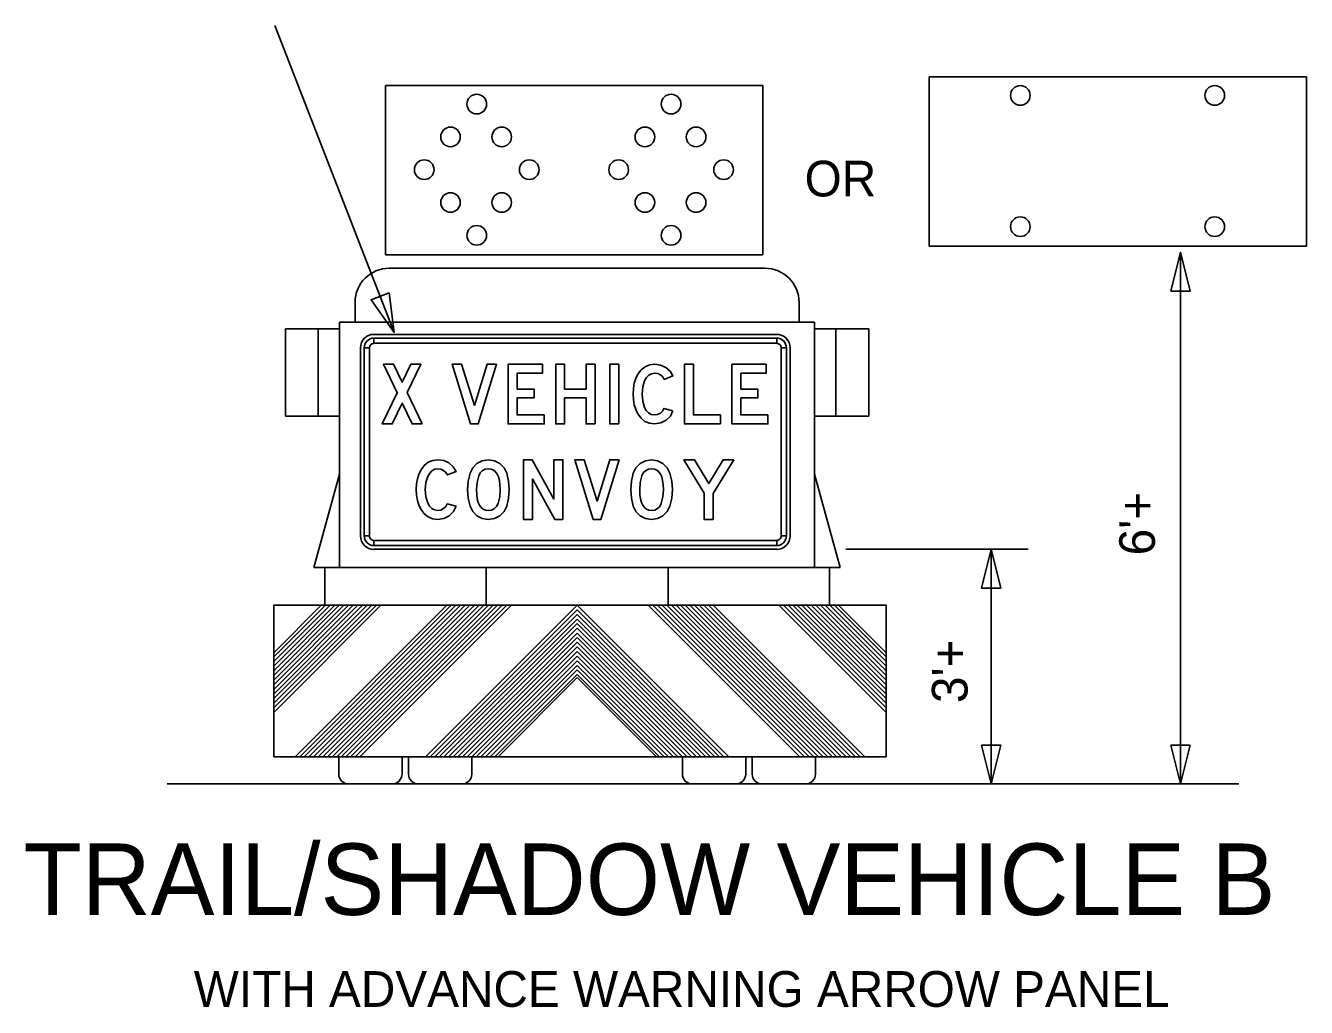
# Model space of a CAD drawing. Extents: x 1806907 to 1812607, y 675071 to 676228.
# Drawn here: x 1811772.8 to 1811988.1, y 675569.5 to 675734.4 of the extents above; entities that cross this region are included whole.
import ezdxf

# ---------------------------------------------------------------- set-up
doc = ezdxf.new("R2010")
doc.units = 0
doc.layers.add('Working Level 1', color=7, linetype='Continuous')

msp = doc.modelspace()

# ---------------------------------------------------------------- linework, layer by layer
at = {"layer": 'Working Level 1'}
for p, q in [((1811834.74, 675682.89), (1811814.73, 675734.43)), ((1811924.67, 675697.37), (1811924.67, 675725.81)), ((1811924.67, 675725.81), (1811988.1, 675725.81)), ((1811988.1, 675697.37), (1811988.1, 675725.81)), ((1811833.29, 675724.36), (1811896.72, 675724.36)), ((1811833.29, 675695.92), (1811833.29, 675724.36)), ((1811896.72, 675695.92), (1811896.72, 675724.36)), ((1811924.67, 675697.37), (1811988.1, 675697.37)), ((1811833.29, 675695.92), (1811896.72, 675695.92)), ((1811966.95, 675607.04), (1811966.95, 675696.35)), ((1811966.95, 675696.35), (1811966.95, 675691.11)), ((1811833.95, 675693.67), (1811897.09, 675693.67)), ((1811828.2, 675684.64), (1811828.2, 675687.94)), ((1811902.83, 675684.64), (1811902.83, 675687.94)), ((1811825.6, 675643.38), (1811825.6, 675684.64)), ((1811825.6, 675684.64), (1811905.43, 675684.64)), ((1811905.43, 675643.38), (1811905.43, 675684.64)), ((1811816.49, 675668.81), (1811816.49, 675683.48)), ((1811816.49, 675683.48), (1811825.6, 675683.48)), ((1811822.01, 675668.81), (1811822.01, 675683.48)), ((1811899.06, 675682.57), (1811831.35, 675682.57)), ((1811831.35, 675681.07), (1811831.35, 675681.94)), ((1811899.06, 675681.94), (1811899.06, 675681.07)), ((1811914.54, 675683.48), (1811905.43, 675683.48)), ((1811909.02, 675668.81), (1811909.02, 675683.48)), ((1811914.54, 675668.81), (1811914.54, 675683.48)), ((1811829.09, 675680.31), (1811829.09, 675648.71)), ((1811829.72, 675680.31), (1811830.59, 675680.31)), ((1811899.81, 675680.31), (1811900.69, 675680.31)), ((1811901.32, 675648.71), (1811901.32, 675680.31)), ((1811816.49, 675668.81), (1811825.6, 675668.81)), ((1811914.54, 675668.81), (1811905.43, 675668.81)), ((1811825.6, 675659.1), (1811821.28, 675643.38)), ((1811905.43, 675659.1), (1811909.75, 675643.38)), ((1811830.59, 675648.71), (1811829.72, 675648.71)), ((1811831.35, 675647.08), (1811831.35, 675647.96)), ((1811899.06, 675647.96), (1811899.06, 675647.08)), ((1811900.69, 675648.71), (1811899.81, 675648.71)), ((1811831.35, 675646.46), (1811899.06, 675646.46)), ((1811910.69, 675646.46), (1811941.31, 675646.46)), ((1811935.14, 675607.04), (1811935.14, 675646.46)), ((1811935.14, 675646.46), (1811935.14, 675641.13)), ((1811821.28, 675643.38), (1811909.75, 675643.38)), ((1811823.08, 675637.07), (1811823.08, 675643.38)), ((1811850.2, 675637.07), (1811850.2, 675643.26)), ((1811880.83, 675637.07), (1811880.83, 675643.26)), ((1811907.95, 675637.07), (1811907.95, 675643.38)), ((1811814.51, 675637.07), (1811917.46, 675637.07)), ((1811814.51, 675637.07), (1811917.46, 675637.07)), ((1811814.51, 675637.07), (1811917.46, 675637.07)), ((1811814.51, 675637.07), (1811917.46, 675637.07)), ((1811814.51, 675611.58), (1811814.51, 675637.07)), ((1811814.51, 675629.09), (1811822.49, 675637.07)), ((1811814.51, 675619.81), (1811831.77, 675637.07)), ((1811814.51, 675620.6), (1811830.99, 675637.07)), ((1811814.51, 675621.38), (1811830.21, 675637.07)), ((1811814.51, 675622.15), (1811829.44, 675637.07)), ((1811814.51, 675622.93), (1811828.65, 675637.07)), ((1811814.51, 675623.71), (1811827.87, 675637.07)), ((1811814.51, 675624.48), (1811827.1, 675637.07)), ((1811814.51, 675625.26), (1811826.32, 675637.07)), ((1811814.51, 675626.04), (1811825.54, 675637.07)), ((1811814.51, 675626.82), (1811824.76, 675637.07)), ((1811814.51, 675627.59), (1811823.99, 675637.07)), ((1811814.51, 675628.37), (1811823.21, 675637.07)), ((1811814.51, 675619.04), (1811832.52, 675637.05)), ((1811818.1, 675611.58), (1811843.6, 675637.07)), ((1811818.88, 675611.58), (1811844.37, 675637.07)), ((1811819.66, 675611.58), (1811845.15, 675637.07)), ((1811820.44, 675611.58), (1811845.94, 675637.07)), ((1811821.21, 675611.58), (1811846.71, 675637.07)), ((1811821.99, 675611.58), (1811847.49, 675637.07)), ((1811822.77, 675611.58), (1811848.27, 675637.07)), ((1811823.55, 675611.58), (1811849.05, 675637.07)), ((1811824.32, 675611.58), (1811849.82, 675637.07)), ((1811825.1, 675611.58), (1811850.6, 675637.07)), ((1811825.88, 675611.58), (1811851.38, 675637.07)), ((1811826.65, 675611.58), (1811852.15, 675637.07)), ((1811827.43, 675611.58), (1811852.93, 675637.07)), ((1811828.21, 675611.58), (1811853.7, 675637.06)), ((1811828.99, 675611.58), (1811854.49, 675637.07)), ((1811840.02, 675611.58), (1811865.52, 675637.07)), ((1811891.01, 675611.58), (1811865.52, 675637.07)), ((1811902.98, 675611.58), (1811877.48, 675637.07)), ((1811903.75, 675611.58), (1811878.26, 675637.06)), ((1811904.53, 675611.58), (1811879.03, 675637.07)), ((1811905.31, 675611.58), (1811879.82, 675637.07)), ((1811906.08, 675611.58), (1811880.59, 675637.07)), ((1811906.86, 675611.58), (1811881.37, 675637.07)), ((1811907.65, 675611.58), (1811882.15, 675637.07)), ((1811908.42, 675611.58), (1811882.92, 675637.07)), ((1811909.2, 675611.58), (1811883.7, 675637.07)), ((1811909.98, 675611.58), (1811884.48, 675637.07)), ((1811910.76, 675611.58), (1811885.26, 675637.07)), ((1811911.53, 675611.58), (1811886.03, 675637.07)), ((1811912.31, 675611.58), (1811886.81, 675637.07)), ((1811913.09, 675611.58), (1811887.59, 675637.07)), ((1811913.87, 675611.58), (1811888.37, 675637.07)), ((1811917.46, 675619.04), (1811899.44, 675637.05)), ((1811917.46, 675619.81), (1811900.2, 675637.07)), ((1811917.46, 675620.6), (1811900.98, 675637.07)), ((1811917.46, 675621.38), (1811901.76, 675637.07)), ((1811917.46, 675622.15), (1811902.53, 675637.07)), ((1811917.46, 675622.93), (1811903.31, 675637.07)), ((1811917.46, 675623.71), (1811904.09, 675637.07)), ((1811917.46, 675624.48), (1811904.86, 675637.07)), ((1811917.46, 675625.26), (1811905.64, 675637.07)), ((1811917.46, 675626.04), (1811906.42, 675637.07)), ((1811917.46, 675626.82), (1811907.21, 675637.07)), ((1811917.46, 675627.59), (1811907.98, 675637.07)), ((1811917.46, 675628.37), (1811908.76, 675637.07)), ((1811917.46, 675629.09), (1811909.48, 675637.07)), ((1811917.46, 675611.58), (1811917.46, 675637.07)), ((1811840.79, 675611.58), (1811865.52, 675636.3)), ((1811841.57, 675611.58), (1811865.52, 675635.52)), ((1811842.35, 675611.58), (1811865.52, 675634.74)), ((1811890.2, 675611.62), (1811865.52, 675636.3)), ((1811889.46, 675611.58), (1811865.52, 675635.52)), ((1811888.68, 675611.58), (1811865.52, 675634.74)), ((1811843.12, 675611.58), (1811865.52, 675633.97)), ((1811843.91, 675611.58), (1811865.52, 675633.19)), ((1811844.69, 675611.58), (1811865.52, 675632.4)), ((1811887.91, 675611.58), (1811865.52, 675633.97)), ((1811887.13, 675611.58), (1811865.52, 675633.19)), ((1811886.35, 675611.58), (1811865.52, 675632.4)), ((1811845.46, 675611.58), (1811865.52, 675631.63)), ((1811846.24, 675611.58), (1811865.52, 675630.85)), ((1811847.02, 675611.58), (1811865.52, 675630.07)), ((1811885.58, 675611.58), (1811865.52, 675631.63)), ((1811884.8, 675611.58), (1811865.52, 675630.85)), ((1811884.02, 675611.58), (1811865.52, 675630.07)), ((1811847.8, 675611.58), (1811865.52, 675629.29)), ((1811848.57, 675611.58), (1811865.52, 675628.52)), ((1811883.24, 675611.58), (1811865.52, 675629.29)), ((1811882.47, 675611.58), (1811865.52, 675628.52)), ((1811849.35, 675611.58), (1811865.52, 675627.74)), ((1811850.13, 675611.58), (1811865.52, 675626.96)), ((1811850.9, 675611.58), (1811865.52, 675626.19)), ((1811881.69, 675611.58), (1811865.52, 675627.74)), ((1811880.9, 675611.58), (1811865.52, 675626.96)), ((1811880.13, 675611.58), (1811865.52, 675626.19)), ((1811851.68, 675611.58), (1811865.52, 675625.41)), ((1811852.33, 675611.72), (1811865.52, 675624.91)), ((1811879.35, 675611.58), (1811865.52, 675625.41)), ((1811878.85, 675611.58), (1811865.52, 675624.91)), ((1811814.51, 675611.58), (1811917.46, 675611.58)), ((1811814.51, 675611.58), (1811917.46, 675611.58)), ((1811814.51, 675611.58), (1811917.46, 675611.58)), ((1811814.51, 675611.58), (1811917.46, 675611.58)), ((1811825.45, 675608.69), (1811825.45, 675611.58)), ((1811836.08, 675608.69), (1811836.08, 675611.58)), ((1811837.18, 675608.69), (1811837.18, 675611.58)), ((1811847.82, 675608.69), (1811847.82, 675611.58)), ((1811883.21, 675608.69), (1811883.21, 675611.58)), ((1811893.85, 675608.69), (1811893.85, 675611.58)), ((1811894.95, 675608.69), (1811894.95, 675611.58)), ((1811905.58, 675608.69), (1811905.58, 675611.58)), ((1811796.63, 675607.04), (1811976.74, 675607.04)), ((1811825.45, 675607.04), (1811836.08, 675607.04)), ((1811825.45, 675607.04), (1811836.08, 675607.04)), ((1811825.45, 675607.04), (1811836.08, 675607.04)), ((1811825.45, 675607.04), (1811836.08, 675607.04)), ((1811837.18, 675607.04), (1811847.82, 675607.04)), ((1811837.18, 675607.04), (1811847.82, 675607.04)), ((1811837.18, 675607.04), (1811847.82, 675607.04)), ((1811837.18, 675607.04), (1811847.82, 675607.04)), ((1811893.85, 675607.04), (1811883.21, 675607.04)), ((1811893.85, 675607.04), (1811883.21, 675607.04)), ((1811893.85, 675607.04), (1811883.21, 675607.04)), ((1811893.85, 675607.04), (1811883.21, 675607.04)), ((1811905.58, 675607.04), (1811894.95, 675607.04)), ((1811905.58, 675607.04), (1811894.95, 675607.04)), ((1811905.58, 675607.04), (1811894.95, 675607.04)), ((1811905.58, 675607.04), (1811894.95, 675607.04))]:
    msp.add_line(p, q, dxfattribs=at)
for points in [[(1811965.32, 675689.85), (1811966.95, 675696.35), (1811968.57, 675689.85)], [(1811833.91, 675689.53), (1811834.74, 675682.89), (1811830.88, 675688.36)], [(1811899.06, 675681.94), (1811831.35, 675681.94), (1811831.35, 675681.07), (1811899.06, 675681.07), (1811899.06, 675681.94)], [(1811829.72, 675680.31), (1811829.72, 675648.71), (1811830.59, 675648.71), (1811830.59, 675680.31), (1811829.72, 675680.31)], [(1811900.69, 675648.71), (1811900.69, 675680.31), (1811899.81, 675680.31), (1811899.81, 675648.71), (1811900.69, 675648.71)], [(1811839.45, 675667.52), (1811836.95, 675672.78), (1811839.24, 675677.55), (1811837.57, 675677.55), (1811836.11, 675674.53), (1811834.67, 675677.55), (1811832.99, 675677.55), (1811835.27, 675672.77), (1811832.76, 675667.52), (1811834.43, 675667.52), (1811836.11, 675671.01), (1811837.77, 675667.52)], [(1811851.98, 675677.55), (1811850.4, 675677.55), (1811848.24, 675670.62), (1811846.09, 675677.55), (1811844.51, 675677.55), (1811847.62, 675667.52), (1811848.86, 675667.52)], [(1811859.98, 675669.04), (1811855.43, 675669.04), (1811855.43, 675671.88), (1811858.27, 675671.88), (1811858.27, 675673.39), (1811855.43, 675673.39), (1811855.43, 675676.04), (1811859.67, 675676.04), (1811859.67, 675677.55), (1811853.92, 675677.55), (1811853.92, 675667.52), (1811859.98, 675667.52)], [(1811868.53, 675667.52), (1811868.53, 675677.55), (1811867.02, 675677.55), (1811867.02, 675673.39), (1811863.42, 675673.39), (1811863.42, 675677.55), (1811861.91, 675677.55), (1811861.91, 675667.52), (1811863.42, 675667.52), (1811863.42, 675671.88), (1811867.02, 675671.88), (1811867.02, 675667.52)], [(1811872.52, 675667.52), (1811872.52, 675677.55), (1811871, 675677.55), (1811871, 675667.52)], [(1811881.62, 675669.75), (1811880.1, 675670.13), (1811879.87, 675669.69), (1811879.51, 675669.34), (1811879.04, 675669.11), (1811878.51, 675669.04), (1811877.99, 675669.12), (1811877.53, 675669.36), (1811877.15, 675669.76), (1811876.85, 675670.31), (1811876.54, 675671.34), (1811876.44, 675672.54), (1811876.54, 675673.74), (1811876.86, 675674.77), (1811877.17, 675675.33), (1811877.57, 675675.72), (1811878.03, 675675.96), (1811878.56, 675676.04), (1811879.06, 675675.97), (1811879.52, 675675.76), (1811879.9, 675675.43), (1811880.16, 675675.01), (1811881.62, 675675.59), (1811881.13, 675676.39), (1811880.41, 675677.02), (1811879.54, 675677.42), (1811878.59, 675677.55), (1811877.7, 675677.45), (1811876.93, 675677.14), (1811876.28, 675676.61), (1811875.73, 675675.88), (1811875.37, 675675.16), (1811875.12, 675674.36), (1811874.97, 675673.49), (1811874.92, 675672.54), (1811874.97, 675671.6), (1811875.12, 675670.73), (1811875.37, 675669.94), (1811875.72, 675669.22), (1811876.26, 675668.47), (1811876.91, 675667.95), (1811877.67, 675667.63), (1811878.54, 675667.52), (1811879.56, 675667.68), (1811880.47, 675668.14), (1811881.19, 675668.85)], [(1811889.61, 675667.52), (1811889.61, 675669.04), (1811885.06, 675669.04), (1811885.06, 675677.55), (1811883.54, 675677.55), (1811883.54, 675667.52)], [(1811897.6, 675669.04), (1811893.05, 675669.04), (1811893.05, 675671.88), (1811895.89, 675671.88), (1811895.89, 675673.39), (1811893.05, 675673.39), (1811893.05, 675676.04), (1811897.29, 675676.04), (1811897.29, 675677.55), (1811891.54, 675677.55), (1811891.54, 675667.52), (1811897.6, 675667.52)], [(1811845.17, 675653.7), (1811843.65, 675654.08), (1811843.43, 675653.64), (1811843.06, 675653.29), (1811842.59, 675653.06), (1811842.07, 675652.99), (1811841.54, 675653.07), (1811841.09, 675653.31), (1811840.71, 675653.71), (1811840.4, 675654.26), (1811840.09, 675655.29), (1811839.99, 675656.49), (1811840.09, 675657.69), (1811840.41, 675658.72), (1811840.73, 675659.28), (1811841.12, 675659.67), (1811841.58, 675659.91), (1811842.12, 675659.99), (1811842.62, 675659.92), (1811843.08, 675659.71), (1811843.46, 675659.38), (1811843.72, 675658.96), (1811845.17, 675659.53), (1811844.68, 675660.34), (1811843.97, 675660.97), (1811843.1, 675661.37), (1811842.14, 675661.5), (1811841.26, 675661.4), (1811840.49, 675661.08), (1811839.83, 675660.56), (1811839.28, 675659.83), (1811838.93, 675659.11), (1811838.68, 675658.31), (1811838.53, 675657.44), (1811838.48, 675656.49), (1811838.52, 675655.55), (1811838.67, 675654.68), (1811838.92, 675653.89), (1811839.28, 675653.16), (1811839.81, 675652.42), (1811840.46, 675651.9), (1811841.22, 675651.58), (1811842.09, 675651.47), (1811843.11, 675651.63), (1811844.03, 675652.09), (1811844.75, 675652.8)], [(1811854.1, 675656.49), (1811854, 675657.93), (1811853.69, 675659.27), (1811853.24, 675660.17), (1811852.52, 675660.89), (1811851.61, 675661.35), (1811850.59, 675661.5), (1811849.57, 675661.35), (1811848.67, 675660.89), (1811847.96, 675660.17), (1811847.51, 675659.26), (1811847.2, 675657.92), (1811847.1, 675656.49), (1811847.2, 675655.07), (1811847.51, 675653.73), (1811847.96, 675652.82), (1811848.67, 675652.1), (1811849.57, 675651.63), (1811850.59, 675651.47), (1811851.61, 675651.63), (1811852.52, 675652.09), (1811853.23, 675652.8), (1811853.68, 675653.71), (1811853.99, 675655.06)], [(1811863.13, 675651.47), (1811863.13, 675661.5), (1811861.61, 675661.5), (1811861.61, 675654.91), (1811857.96, 675661.5), (1811856.5, 675661.5), (1811856.5, 675651.47), (1811858.02, 675651.47), (1811858.02, 675658.28), (1811861.79, 675651.47)], [(1811872.59, 675661.5), (1811871.01, 675661.5), (1811868.86, 675654.57), (1811866.71, 675661.5), (1811865.12, 675661.5), (1811868.23, 675651.47), (1811869.48, 675651.47)], [(1811881.53, 675656.49), (1811881.43, 675657.93), (1811881.12, 675659.27), (1811880.67, 675660.17), (1811879.95, 675660.89), (1811879.04, 675661.35), (1811878.02, 675661.5), (1811877, 675661.35), (1811876.1, 675660.89), (1811875.39, 675660.17), (1811874.94, 675659.26), (1811874.63, 675657.92), (1811874.53, 675656.49), (1811874.63, 675655.07), (1811874.94, 675653.73), (1811875.39, 675652.82), (1811876.1, 675652.1), (1811877, 675651.63), (1811878.02, 675651.47), (1811879.04, 675651.63), (1811879.95, 675652.09), (1811880.66, 675652.8), (1811881.12, 675653.71), (1811881.42, 675655.06)], [(1811891.87, 675661.5), (1811890.09, 675661.5), (1811887.63, 675657.5), (1811885.23, 675661.5), (1811883.46, 675661.5), (1811886.87, 675655.87), (1811886.87, 675651.47), (1811888.38, 675651.47), (1811888.38, 675655.83)], [(1811852.59, 675656.49), (1811852.5, 675655.27), (1811852.23, 675654.14), (1811851.99, 675653.66), (1811851.61, 675653.3), (1811851.14, 675653.06), (1811850.61, 675652.99), (1811850.14, 675653.04), (1811849.73, 675653.21), (1811849.39, 675653.48), (1811849.11, 675653.86), (1811848.89, 675654.35), (1811848.74, 675654.96), (1811848.64, 675655.67), (1811848.61, 675656.49), (1811848.7, 675657.7), (1811848.97, 675658.83), (1811849.21, 675659.3), (1811849.58, 675659.67), (1811850.06, 675659.91), (1811850.61, 675659.99), (1811851.07, 675659.93), (1811851.47, 675659.77), (1811851.81, 675659.5), (1811852.09, 675659.11), (1811852.31, 675658.62), (1811852.46, 675658.02), (1811852.55, 675657.31)], [(1811880.02, 675656.49), (1811879.93, 675655.27), (1811879.66, 675654.14), (1811879.42, 675653.66), (1811879.04, 675653.3), (1811878.57, 675653.06), (1811878.04, 675652.99), (1811877.57, 675653.04), (1811877.16, 675653.21), (1811876.82, 675653.48), (1811876.54, 675653.86), (1811876.32, 675654.35), (1811876.17, 675654.96), (1811876.07, 675655.67), (1811876.04, 675656.49), (1811876.13, 675657.7), (1811876.4, 675658.83), (1811876.64, 675659.3), (1811877.01, 675659.67), (1811877.49, 675659.91), (1811878.04, 675659.99), (1811878.5, 675659.93), (1811878.9, 675659.77), (1811879.24, 675659.5), (1811879.52, 675659.11), (1811879.74, 675658.62), (1811879.89, 675658.02), (1811879.98, 675657.31)], [(1811831.35, 675647.08), (1811899.06, 675647.08), (1811899.06, 675647.96), (1811831.35, 675647.96), (1811831.35, 675647.08)], [(1811933.51, 675639.96), (1811935.14, 675646.46), (1811936.76, 675639.96)], [(1811936.76, 675613.54), (1811935.14, 675607.04), (1811933.51, 675613.54)], [(1811968.57, 675613.54), (1811966.95, 675607.04), (1811965.32, 675613.54)]]:
    msp.add_lwpolyline(points, close=True, dxfattribs=at)
for centre in [(1811848.64, 675721.25), (1811881.32, 675721.25), (1811940.02, 675722.7), (1811972.7, 675722.7), (1811844.23, 675715.74), (1811852.84, 675715.74), (1811876.91, 675715.74), (1811885.52, 675715.74), (1811839.82, 675710.23), (1811857.46, 675710.23), (1811872.5, 675710.23), (1811890.14, 675710.23), (1811844.23, 675704.72), (1811852.84, 675704.72), (1811876.91, 675704.72), (1811885.52, 675704.72), (1811940.02, 675700.66), (1811972.7, 675700.66), (1811848.64, 675699.2), (1811881.32, 675699.2)]:
    msp.add_circle(centre, 1.65, dxfattribs=at)
for centre, radius, start, end in [((1811833.94, 675687.94), 5.74, 90, 180), ((1811897.09, 675687.94), 5.74, 0, 90), ((1811831.35, 675680.31), 2.26, 90.0002, 179.9998), ((1811831.35, 675680.31), 1.63, 90.0002, 179.9998), ((1811899.06, 675680.31), 2.26, 0, 90.0002), ((1811899.06, 675680.31), 1.63, 0, 90.0002), ((1811831.35, 675680.31), 0.752, 90.0002, 179.9998), ((1811899.06, 675680.31), 0.752, 0, 90.0002), ((1811831.35, 675648.71), 2.26, 179.9998, 270.0001), ((1811831.35, 675648.71), 1.63, 179.9998, 270.0001), ((1811831.35, 675648.71), 0.752, 179.9998, 270.0001), ((1811899.06, 675648.71), 2.26, 270.0001, 0.0003), ((1811899.06, 675648.71), 1.63, 270.0001, 0.0003), ((1811899.06, 675648.71), 0.752, 270.0001, 0.0003), ((1811827.1, 675608.69), 1.65, 180, 270), ((1811834.43, 675608.69), 1.65, 270, 0), ((1811838.83, 675608.69), 1.65, 180, 270), ((1811846.17, 675608.69), 1.65, 270, 0), ((1811884.86, 675608.69), 1.65, 180, 270), ((1811892.2, 675608.69), 1.65, 270, 0), ((1811896.6, 675608.69), 1.65, 180, 270), ((1811903.93, 675608.69), 1.65, 270, 0)]:
    msp.add_arc(centre, radius, start, end, dxfattribs=at)

# ---------------------------------------------------------------- texts
for s, height, p in [('OR', 6, (1811903.76, 675705.74)), ('TRAIL/SHADOW VEHICLE B', 12, (1811772.45, 675585.04)), ('WITH ADVANCE WARNING ARROW PANEL', 6, (1811801.08, 675569.6))]:
    msp.add_text(s, height=height, dxfattribs=at).set_placement(p)
for s, p in [("6'+", (1811962.65, 675645.44)), ("3'+", (1811931.15, 675620.63))]:
    msp.add_text(s, height=6, rotation=90, dxfattribs=at).set_placement(p)

doc.saveas('drawing.dxf')
